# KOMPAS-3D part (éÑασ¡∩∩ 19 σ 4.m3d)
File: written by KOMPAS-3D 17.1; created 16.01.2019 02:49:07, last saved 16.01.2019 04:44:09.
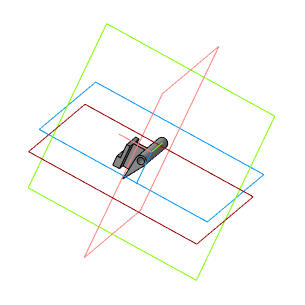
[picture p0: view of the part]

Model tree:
1. Эскиз:1
2. Элемент выдавливания:1
     Расстояние 1 = 9.5; Расстояние 2 = 9.5
3. Смещенная плоскость:1
     Расстояние = 6.76
4. Клин
5. Элемент выдавливания:2
     Расстояние 1 = 6.76
6. Эскиз:3
7. Элемент выдавливания:3
     Расстояние 1 = 3
8. Эскиз:4
9. Элемент выдавливания:4
     Расстояние 2 = 4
